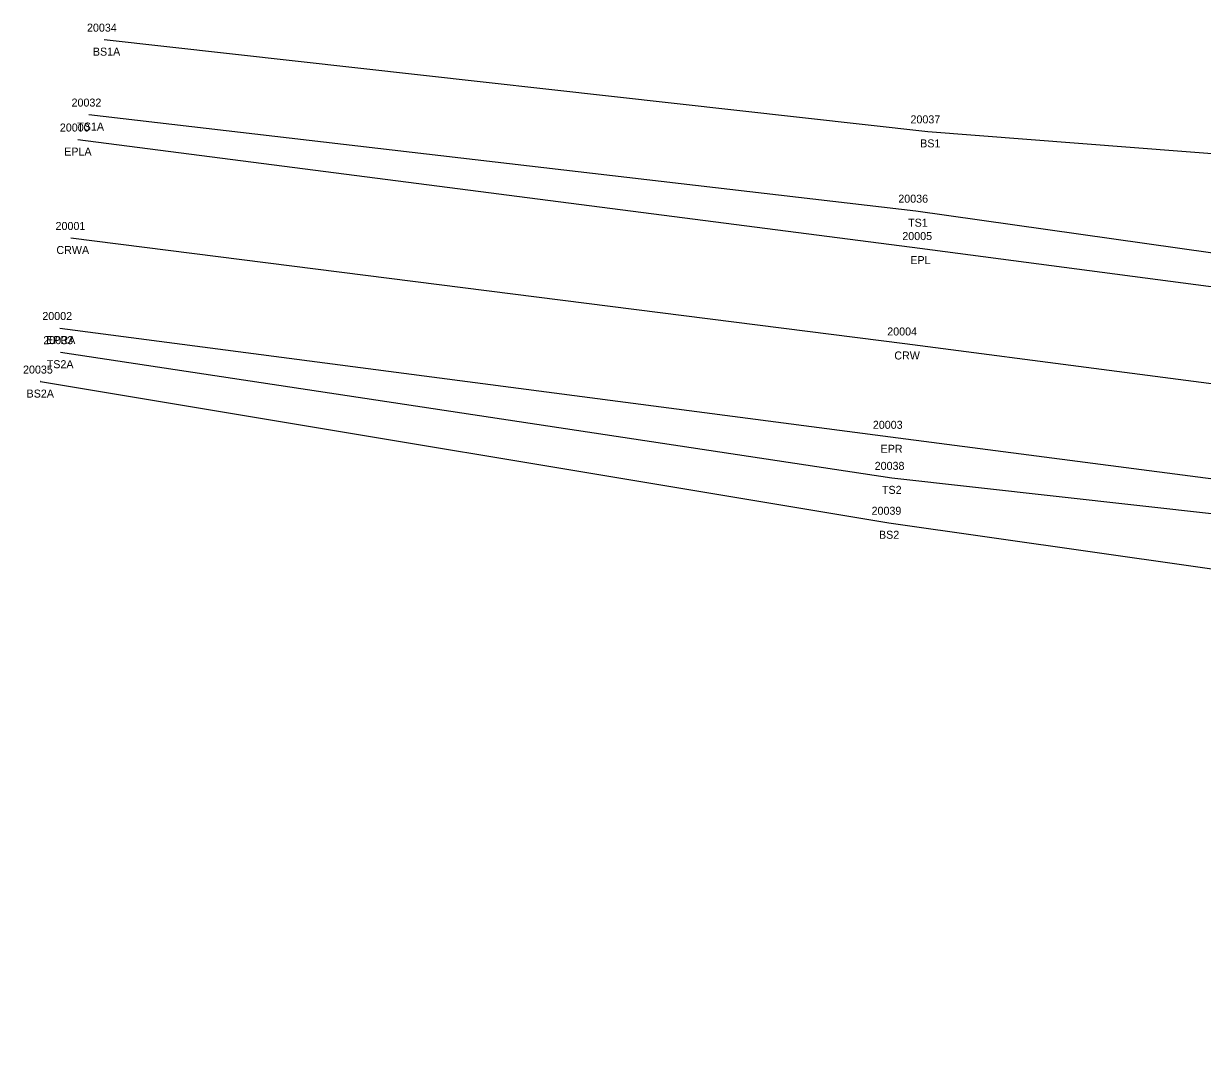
# Model space of a CAD drawing. Extents: x 2080935 to 2082049, y 730754 to 730962.
# Drawn here: x 2080935.3 to 2081082.6, y 730833.2 to 730961.9 of the extents above; entities that cross this region are included whole.
import ezdxf

# ---------------------------------------------------------------- set-up
doc = ezdxf.new("R2010")
doc.units = 0
for name, color, linetype in [('RD_DTM_BkLn1', 7, 'Continuous'), ('RD_DTM_BkLn2', 7, 'Continuous'), ('RD_EX_Road', 7, 'Continuous'), ('RD_EX_Road_txCode', 7, 'Continuous'), ('RD_SMD_Locator', 7, 'Continuous'), ('RD_SMD_Misc', 7, 'Continuous')]:
    doc.layers.add(name, color=color, linetype=linetype)

msp = doc.modelspace()

# ---------------------------------------------------------------- linework, layer by layer
at = {"layer": 'RD_DTM_BkLn1'}
msp.add_lwpolyline([(2080941.25, 730935.08), (2081045.42, 730921.9), (2081147.52, 730908.57), (2081249.67, 730895.22), (2081352.74, 730881.46), (2081412.15, 730874.37), (2081469.7, 730866.51)], dxfattribs=at)
at = {"layer": 'RD_DTM_BkLn2'}
for points in [[(2080945.43, 730959.86), (2081048.27, 730948.4), (2081150.46, 730940.47), (2081258.15, 730927.34), (2081357.17, 730920.11)], [(2080943.5, 730950.5), (2081046.79, 730938.49), (2081149.23, 730923.98), (2081252.89, 730918.53), (2081354.86, 730896.89)], [(2080939.97, 730920.81), (2081043.8, 730905.11), (2081146.06, 730893.71), (2081210.56, 730884.9), (2081214.62, 730886.52)], [(2080937.44, 730917.14), (2081043.42, 730899.5), (2081145.18, 730884.99), (2081213.57, 730879.31), (2081219.84, 730884.63), (2081248.03, 730882.14), (2081293.17, 730875.78), (2081295.97, 730870.07), (2081341.8, 730864.37), (2081343.7, 730868.33), (2081350.17, 730868.41), (2081364.36, 730860.34), (2081384.26, 730854.27), (2081383.97, 730833.2)]]:
    msp.add_lwpolyline(points, dxfattribs=at)
at = {"layer": 'RD_EX_Road'}
for points in [[(2080942.12, 730947.38), (2081047.3, 730933.82), (2081149.12, 730920.41), (2081250.8, 730907.26), (2081354.36, 730894.35), (2081413.29, 730885.99), (2081474.17, 730877.58), (2081469.7, 730866.51)], [(2080939.88, 730923.83), (2081043.62, 730910.24), (2081146.95, 730896.77), (2081220.01, 730886.78), (2081221.02, 730889.92), (2081249.39, 730886.24), (2081293.86, 730880.24), (2081293.66, 730877.5), (2081351.01, 730869.76), (2081411.83, 730862.33), (2081465.27, 730855.52), (2081469.7, 730866.51)]]:
    msp.add_lwpolyline(points, dxfattribs=at)
at = {"layer": 'RD_SMD_Locator'}
for centre in [(2080945.43, 730959.86), (2080943.5, 730950.5), (2081048.27, 730948.4), (2080942.12, 730947.38), (2081046.79, 730938.49), (2080941.25, 730935.08), (2081047.3, 730933.82), (2080939.88, 730923.83), (2081045.42, 730921.9), (2080939.97, 730920.81), (2080937.44, 730917.14), (2081043.62, 730910.24), (2081043.8, 730905.11), (2081043.42, 730899.5)]:
    msp.add_circle(centre, 0.001, dxfattribs=at)

# ---------------------------------------------------------------- texts
at = {"layer": 'RD_EX_Road_txCode'}
for s, p in [('20000', (2080939.88, 730948.38)), ('EPLA', (2080940.42, 730945.38)), ('20005', (2081045.1, 730934.82)), ('EPL', (2081046.1, 730931.82)), ('20002', (2080937.69, 730924.83)), ('EPRA', (2080938.17, 730921.83)), ('20003', (2081041.42, 730911.24)), ('EPR', (2081042.39, 730908.24))]:
    msp.add_text(s, height=1, dxfattribs=at).set_placement(p)
at = {"layer": 'RD_SMD_Misc'}
for s, p in [('20034', (2080943.27, 730960.86)), ('BS1A', (2080944, 730957.86)), ('20032', (2080941.34, 730951.5)), ('20037', (2081046.12, 730949.4)), ('TS1A', (2080942.05, 730948.5)), ('BS1', (2081047.33, 730946.4)), ('20036', (2081044.6, 730939.49)), ('TS1', (2081045.82, 730936.49)), ('20001', (2080939.34, 730936.08)), ('CRWA', (2080939.45, 730933.08)), ('20004', (2081043.22, 730922.9)), ('20033', (2080937.81, 730921.81)), ('TS2A', (2080938.24, 730918.81)), ('CRW', (2081044.1, 730919.9)), ('20035', (2080935.28, 730918.14)), ('BS2A', (2080935.72, 730915.14)), ('20038', (2081041.65, 730906.11)), ('TS2', (2081042.56, 730903.11)), ('20039', (2081041.26, 730900.5)), ('BS2', (2081042.19, 730897.5))]:
    msp.add_text(s, height=1, dxfattribs=at).set_placement(p)

doc.saveas('drawing.dxf')
